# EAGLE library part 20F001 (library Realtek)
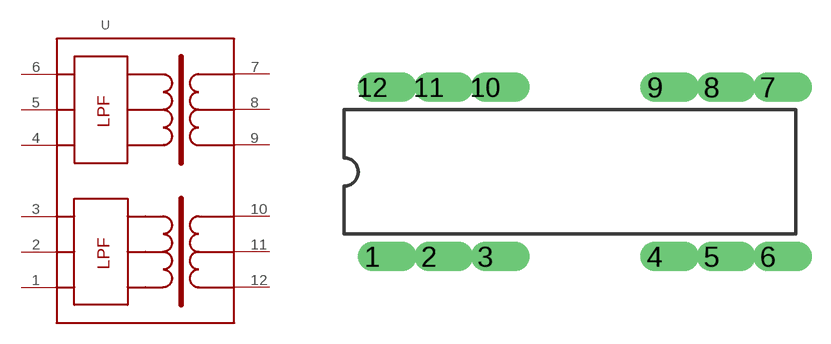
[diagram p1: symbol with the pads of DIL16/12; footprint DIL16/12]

Designator prefix -

## 20F001  [DIL16/12]
1  P$1
2  P$2
3  P$3
4  P$4
5  P$5
6  P$6
7  P$7
8  P$8
9  P$9
10  P$10
11  P$11
12  P$12

## Footprint DIL16/12 (pad centres in mm)
drill 0.813 offset: 1 -8.89,-3.81; 2 -6.35,-3.81; 3 -3.81,-3.81; 4 3.81,-3.81; 5 6.35,-3.81; 6 8.89,-3.81; 7 8.89,3.81; 8 6.35,3.81; 9 3.81,3.81; 10 -3.81,3.81; 11 -6.35,3.81; 12 -8.89,3.81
